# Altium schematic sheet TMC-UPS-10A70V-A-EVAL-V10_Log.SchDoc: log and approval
size A4; CompanyName: Hedgehog OÜ; SheetNumber: 5; SheetTotal: 5; Author: Peep Narusberg; DrawnBy: Peep Narusberg; Engineer: Peep Narusberg; Organization: Hedgehog OÜ; Address1: Waterloohain 5; Address2: 22769 Hamburg; Address3: Germany; Address4: tmc_info@trinamic.com
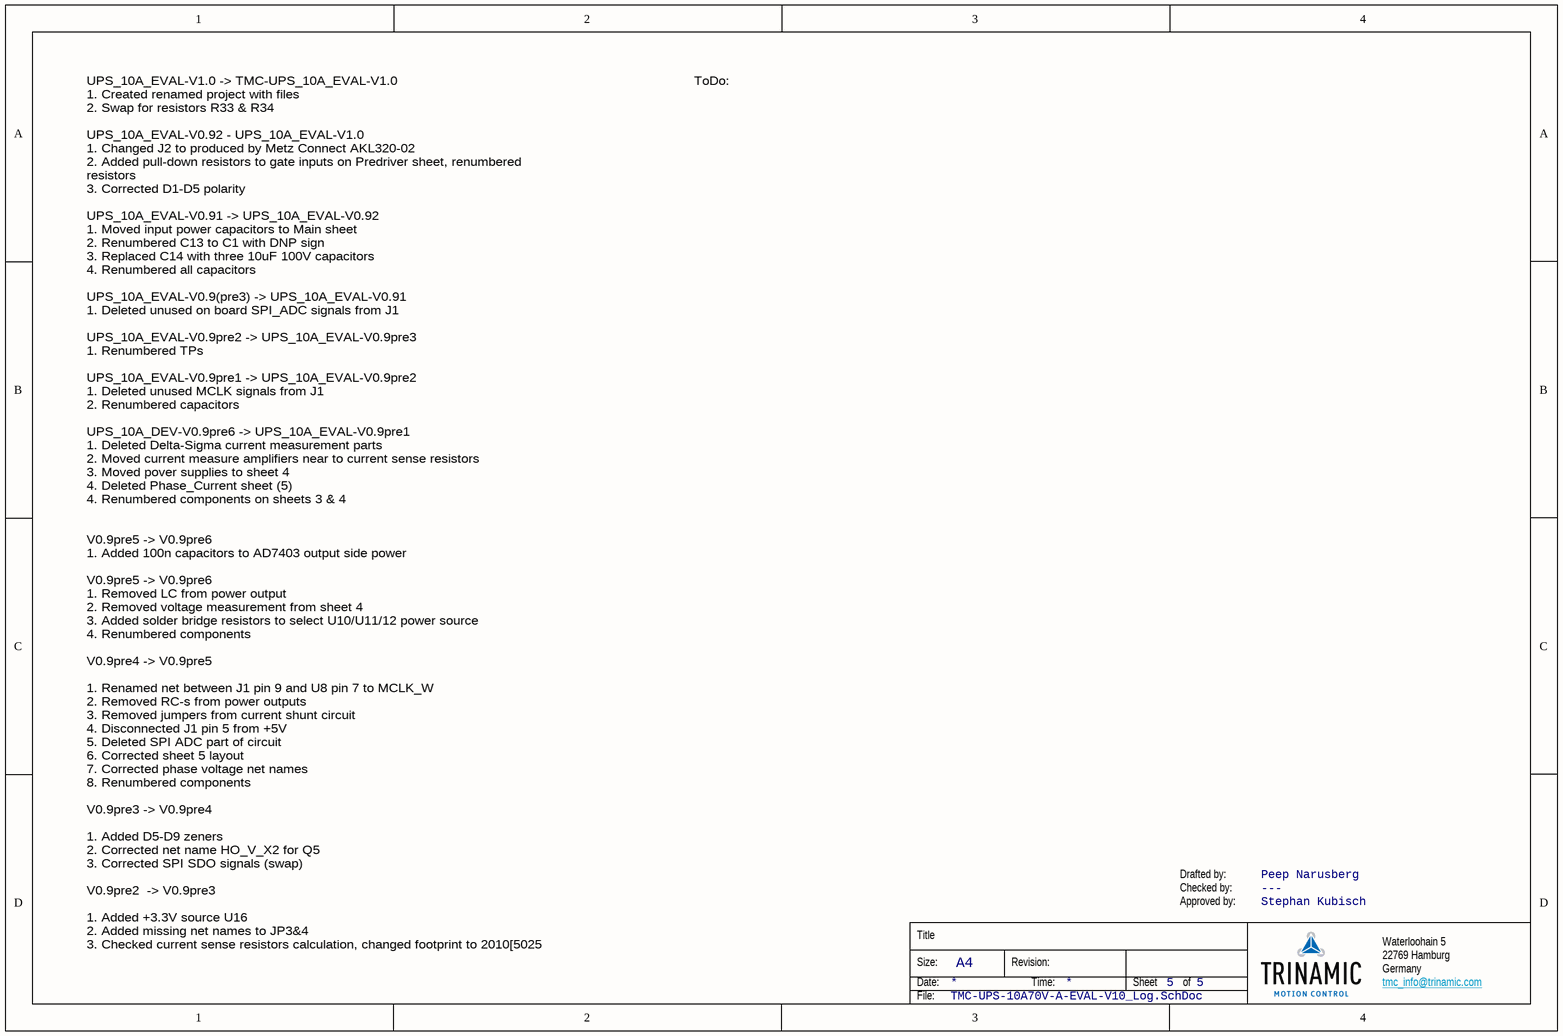
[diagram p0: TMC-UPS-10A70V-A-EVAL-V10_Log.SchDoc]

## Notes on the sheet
- ToDo:
- Drafted by:
- Checked by:
- Approved by:
- Peep Narusberg
- ---
- Stephan Kubisch
- UPS_10A_EVAL-V1.0 -> TMC-UPS_10A_EVAL-V1.0
  1. Created renamed project with files
  2. Swap for resistors R33 & R34
  UPS_10A_EVAL-V0.92 - UPS_10A_EVAL-V1.0
  1. Changed J2 to produced by Metz Connect AKL320-02
  2. Added pull-down resistors to gate inputs on Predriver sheet, renumbered resistors
  3. Corrected D1-D5 polarity
  UPS_10A_EVAL-V0.91 -> UPS_10A_EVAL-V0.92
  1. Moved input power capacitors to Main sheet
  2. Renumbered C13 to C1 with DNP sign
  3. Replaced C14 with three 10uF 100V capacitors
  4. Renumbered all capacitors
  UPS_10A_EVAL-V0.9(pre3) -> UPS_10A_EVAL-V0.91
  1. Deleted unused on board SPI_ADC signals from J1
  UPS_10A_EVAL-V0.9pre2 -> UPS_10A_EVAL-V0.9pre3
  1. Renumbered TPs
  UPS_10A_EVAL-V0.9pre1 -> UPS_10A_EVAL-V0.9pre2
  1. Deleted unused MCLK signals from J1
  2. Renumbered capacitors
  UPS_10A_DEV-V0.9pre6 -> UPS_10A_EVAL-V0.9pre1
  1. Deleted Delta-Sigma current measurement parts
  2. Moved current measure amplifiers near to current sense resistors
  3. Moved pover supplies to sheet 4
  4. Deleted Phase_Current sheet (5)
  4. Renumbered components on sheets 3 & 4
  V0.9pre5 -> V0.9pre6
  1. Added 100n capacitors to AD7403 output side power
  V0.9pre5 -> V0.9pre6
  1. Removed LC from power output
  2. Removed voltage measurement from sheet 4
  3. Added solder bridge resistors to select U10/U11/12 power source
  4. Renumbered components
  V0.9pre4 -> V0.9pre5
  1. Renamed net between J1 pin 9 and U8 pin 7 to MCLK_W
  2. Removed RC-s from power outputs
  3. Removed jumpers from current shunt circuit
  4. Disconnected J1 pin 5 from +5V
  5. Deleted SPI ADC part of circuit
  6. Corrected sheet 5 layout
  7. Corrected phase voltage net names
  8. Renumbered components
  V0.9pre3 -> V0.9pre4
  1. Added D5-D9 zeners
  2. Corrected net name HO_V_X2 for Q5
  3. Corrected SPI SDO signals (swap)
  V0.9pre2  -> V0.9pre3
  1. Added +3.3V source U16
  2. Added missing net names to JP3&4
  3. Checked current sense resistors calculation, changed footprint to 2010[5025 Metric]
  V0.9pre1 -> V0.9pre2
  1. Corrected net and port names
